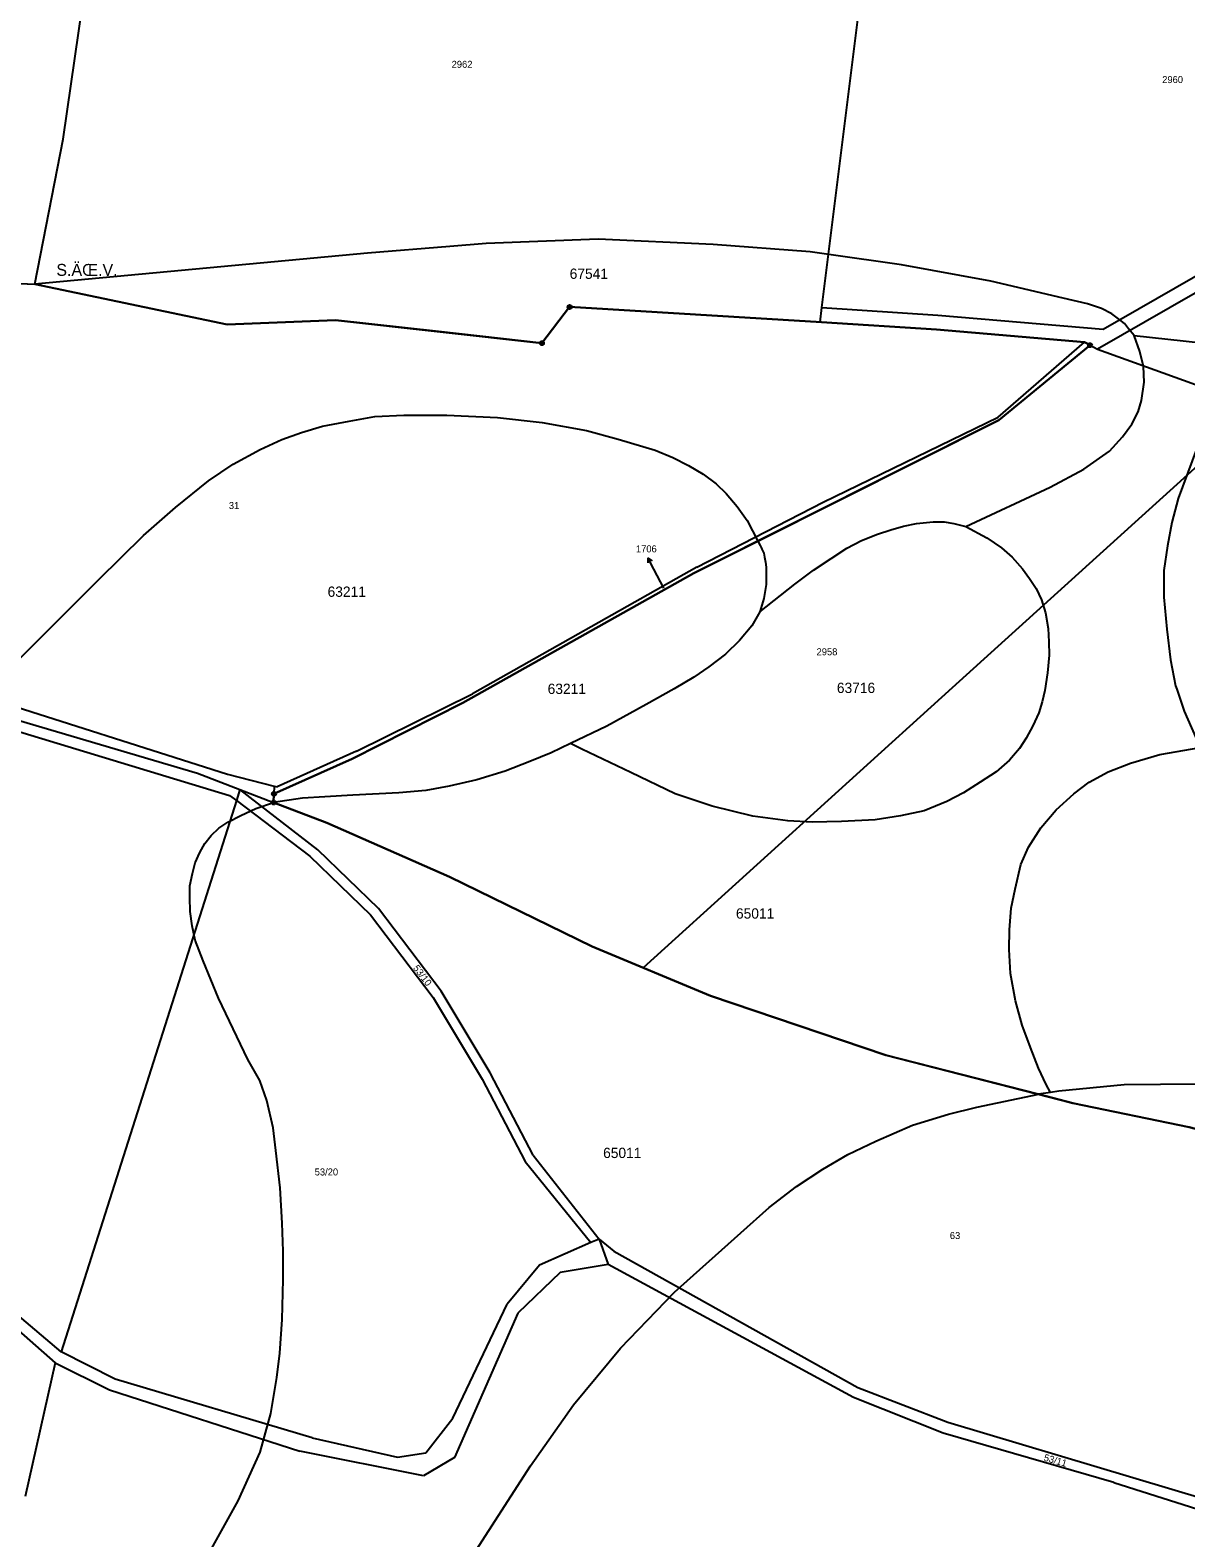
# Model space of a CAD drawing. Extents: x -546762 to -540209, y -1046851 to -1035694.
# Drawn here: x -544167.4 to -543886.8, y -1040941.9 to -1040575.9 of the extents above; entities that cross this region are included whole.
import ezdxf

# ---------------------------------------------------------------- set-up
doc = ezdxf.new("R2010")
doc.units = 0
for name, color, linetype in [('Vrstva 1', 7, 'Continuous'), ('Vrstva 13', 7, 'Continuous'), ('Vrstva 15', 7, 'Continuous'), ('Vrstva 16', 7, 'Continuous'), ('Vrstva 18', 7, 'Continuous'), ('Vrstva 24', 7, 'Continuous'), ('Vrstva 52', 7, 'Continuous'), ('Vrstva 53', 7, 'Continuous'), ('Vrstva 6', 7, 'Continuous')]:
    doc.layers.add(name, color=color, linetype=linetype)

msp = doc.modelspace()

# ---------------------------------------------------------------- linework, layer by layer
at = {"layer": 'Vrstva 1'}
for p, q in [((-543932.34, -1040669.86), (-543911.39, -1040651.66)), ((-544116.45, -1040760.23), (-544108.27, -1040763.37)), ((-544108.12, -1040759.38), (-544108.19, -1040761.26))]:
    msp.add_line(p, q, dxfattribs=at)
for points in [[(-543975.15, -1040643.22), (-543960.77, -1040527.96)], [(-543906.8, -1040648.49), (-543749.51, -1040558.14)], [(-543790.22, -1040585.7), (-543908.23, -1040653.37)], [(-543975.59, -1040646.75), (-543975.15, -1040643.22)], [(-543975.15, -1040643.22), (-543947.02, -1040645.05)], [(-543947.02, -1040645.05), (-543906.8, -1040648.49)], [(-543910.01, -1040652.36), (-543908.23, -1040653.37)], [(-543908.23, -1040653.37), (-543868.48, -1040667.62)], [(-543868.48, -1040667.62), (-543943.52, -1040735.55)], [(-543943.52, -1040735.55), (-544018.57, -1040803.47)], [(-544177.14, -1040885.51), (-544161.29, -1040899.35)], [(-544161.29, -1040899.35), (-544168.58, -1040931.83)]]:
    msp.add_lwpolyline(points, dxfattribs=at)
at = {"layer": 'Vrstva 13'}
msp.add_line((-544194.81, -1040636.28), (-544166.22, -1040637.59), dxfattribs=at)
for points in [[(-544159.37, -1040602.39), (-544152.78, -1040556.39)], [(-544166.22, -1040637.59), (-544159.37, -1040602.39)], [(-544166.22, -1040637.59), (-544119.59, -1040647.38)], [(-544166.22, -1040637.59), (-544119.59, -1040647.38)], [(-544036.41, -1040643.09), (-544043.13, -1040651.87)], [(-544036.41, -1040643.09), (-544043.13, -1040651.87)], [(-543975.59, -1040646.75), (-544036.41, -1040643.09)], [(-543975.59, -1040646.75), (-544036.41, -1040643.09)], [(-544119.59, -1040647.38), (-544093.27, -1040646.28)], [(-544119.59, -1040647.38), (-544093.27, -1040646.28)], [(-544043.13, -1040651.87), (-544093.27, -1040646.28)], [(-544043.13, -1040651.87), (-544093.27, -1040646.28)], [(-543975.26, -1040646.77), (-543975.59, -1040646.75)], [(-543975.26, -1040646.77), (-543975.59, -1040646.75)], [(-543975.26, -1040646.77), (-543947.29, -1040648.59)], [(-543975.26, -1040646.77), (-543947.29, -1040648.59)], [(-543947.29, -1040648.59), (-543911.39, -1040651.66)], [(-543947.29, -1040648.59), (-543911.39, -1040651.66)], [(-543910.01, -1040652.36), (-543932.13, -1040670.57)], [(-543910.01, -1040652.36), (-543932.13, -1040670.57)], [(-543910.01, -1040652.36), (-543911.39, -1040651.66)], [(-543910.01, -1040652.36), (-543911.39, -1040651.66)], [(-543932.13, -1040670.57), (-544006.25, -1040707.73)], [(-543932.13, -1040670.57), (-544006.25, -1040707.73)], [(-544006.25, -1040707.73), (-544062.36, -1040739.14)], [(-544006.25, -1040707.73), (-544062.36, -1040739.14)], [(-544062.36, -1040739.14), (-544089.23, -1040752.75)], [(-544062.36, -1040739.14), (-544089.23, -1040752.75)], [(-544108.19, -1040761.26), (-544089.23, -1040752.75)], [(-544108.19, -1040761.26), (-544089.23, -1040752.75)], [(-544108.27, -1040763.37), (-544108.19, -1040761.26)], [(-544108.27, -1040763.37), (-544108.19, -1040761.26)], [(-544095.39, -1040768.31), (-544108.27, -1040763.37)], [(-544095.39, -1040768.31), (-544108.27, -1040763.37)], [(-544095.39, -1040768.31), (-544065.53, -1040781.42)], [(-544095.39, -1040768.31), (-544065.53, -1040781.42)], [(-544065.53, -1040781.42), (-544030.94, -1040798.31)], [(-544065.53, -1040781.42), (-544030.94, -1040798.31)], [(-544018.57, -1040803.47), (-544030.94, -1040798.31)], [(-544018.57, -1040803.47), (-544030.94, -1040798.31)], [(-544002.2, -1040810.3), (-544018.57, -1040803.47)], [(-544002.2, -1040810.3), (-544018.57, -1040803.47)], [(-544002.2, -1040810.3), (-543959.63, -1040824.69)], [(-544002.2, -1040810.3), (-543959.63, -1040824.69)], [(-543959.63, -1040824.69), (-543914.18, -1040836.33)], [(-543959.63, -1040824.69), (-543914.18, -1040836.33)], [(-543914.18, -1040836.33), (-543885.98, -1040842.13)], [(-543914.18, -1040836.33), (-543885.98, -1040842.13)]]:
    msp.add_lwpolyline(points, dxfattribs=at)
at = {"layer": 'Vrstva 16'}
msp.add_line((-544015.93, -1040706.72), (-544017.29, -1040704.05), dxfattribs=at)
for points in [[(-544017.29, -1040705.17), (-544017.29, -1040704.05), (-544016.39, -1040704.71)], [(-544013.55, -1040711.37), (-544015.93, -1040706.72)]]:
    msp.add_lwpolyline(points, dxfattribs=at)
at = {"layer": 'Vrstva 24'}
for centre, radius in [((-544036.41, -1040643.09), 0.5), ((-544036.41, -1040643.09), 0.1), ((-544043.13, -1040651.87), 0.5), ((-544043.13, -1040651.87), 0.1), ((-543910.01, -1040652.36), 0.5), ((-543910.01, -1040652.36), 0.1), ((-544108.19, -1040761.26), 0.5), ((-544108.19, -1040761.26), 0.1), ((-544108.27, -1040763.37), 0.5), ((-544108.27, -1040763.37), 0.1)]:
    msp.add_circle(centre, radius, dxfattribs=at)
at = {"layer": 'Vrstva 52'}
for points in [[(-544166.22, -1040637.59), (-544159.37, -1040602.39), (-544152.78, -1040556.39), (-544148.25, -1040518.25), (-544148.05, -1040516.52), (-544147.1, -1040509.05), (-544119.61, -1040511.85), (-544114.36, -1040467.79), (-544109.21, -1040427.07), (-544107.28, -1040390.92), (-544084.37, -1040386.84), (-544033.06, -1040401.65), (-543986.48, -1040373.41), (-543990.67, -1040372.14), (-543961.4, -1040311.25), (-543946.79, -1040291.41)], [(-543910.66, -1040642.36), (-543916.57, -1040640.99), (-543934.09, -1040636.81), (-543955.78, -1040632.89), (-543973.45, -1040630.39), (-543978, -1040629.75), (-544001.53, -1040627.92), (-544029.5, -1040626.61), (-544056.68, -1040627.66), (-544065.45, -1040628.38), (-544085.44, -1040630.01), (-544166.22, -1040637.59)], [(-544297.7, -1040664.73), (-544298.67, -1040642.1), (-544267.15, -1040646.48), (-544246.26, -1040643.8), (-544216.62, -1040644.41), (-544194.81, -1040636.28), (-544166.22, -1040637.59)], [(-544166.22, -1040637.59), (-544119.59, -1040647.38), (-544093.27, -1040646.28), (-544043.13, -1040651.87), (-544036.41, -1040643.09), (-543975.26, -1040646.77), (-543947.29, -1040648.59), (-543911.39, -1040651.66), (-543910.01, -1040652.36), (-543932.13, -1040670.57), (-543990.72, -1040699.94)], [(-543990.71, -1040699.94), (-543932.13, -1040670.57), (-543910.01, -1040652.36), (-543911.39, -1040651.66), (-543947.29, -1040648.59), (-543975.26, -1040646.77), (-544036.41, -1040643.09), (-544043.13, -1040651.87), (-544068.2, -1040649.08), (-544093.27, -1040646.28), (-544119.59, -1040647.38), (-544166.22, -1040637.59)], [(-543899.3, -1040650.05), (-543900.69, -1040648.36), (-543901.69, -1040647.14), (-543903.46, -1040645.77), (-543904.77, -1040644.75), (-543907.24, -1040643.47), (-543910.66, -1040642.36)], [(-543940.17, -1040696.35), (-543919.71, -1040686.79), (-543911.49, -1040682.45), (-543905.28, -1040678.06), (-543902.12, -1040674.64), (-543899.9, -1040671.57), (-543898.36, -1040668.58), (-543897.51, -1040665.76), (-543896.91, -1040661.32), (-543897.08, -1040657.56), (-543897.94, -1040653.89), (-543899.3, -1040650.05)], [(-543899.3, -1040650.05), (-543874.8, -1040652.69)], [(-543874.8, -1040652.69), (-543882.91, -1040674.14), (-543888.66, -1040689.57), (-543890.15, -1040695.43), (-543891.2, -1040701.11), (-543892.09, -1040707.08), (-543892.09, -1040713.51), (-543891.35, -1040721.28), (-543890.45, -1040728.75), (-543889.26, -1040735.03), (-543888.98, -1040735.84), (-543887.17, -1040741.16), (-543883.28, -1040749.98)], [(-544176.07, -1040734.52), (-544150.81, -1040709.32), (-544139.86, -1040698.54), (-544132.11, -1040691.75), (-544124.12, -1040685.33), (-544118.06, -1040681.21), (-544111.52, -1040677.7), (-544106.32, -1040675.27), (-544101.47, -1040673.58), (-544096.39, -1040672), (-544089.97, -1040670.79), (-544083.67, -1040669.7), (-544076.65, -1040669.33), (-544066.23, -1040669.33), (-544053.88, -1040669.94), (-544043.1, -1040671.15), (-544032.32, -1040673.09), (-544024.57, -1040675.15), (-544015.61, -1040677.82), (-544011.3, -1040679.63), (-544007.49, -1040681.57), (-544003.96, -1040683.65), (-544000.85, -1040686), (-543998.36, -1040688.36), (-543995.73, -1040691.54), (-543993.31, -1040694.94), (-543990.72, -1040699.94)], [(-543990.18, -1040717.05), (-543981.69, -1040710.41), (-543977.16, -1040706.99), (-543972.91, -1040704.11), (-543969.06, -1040701.63), (-543965.5, -1040699.77), (-543961.65, -1040698.21), (-543958.38, -1040697.18), (-543955.36, -1040696.31), (-543952.19, -1040695.67), (-543948.14, -1040695.28), (-543945.41, -1040695.28), (-543943.06, -1040695.62), (-543940.17, -1040696.35)], [(-543940.17, -1040696.35), (-543935.12, -1040699.16), (-543931.54, -1040701.55), (-543928.95, -1040703.79), (-543926.41, -1040706.62), (-543924.71, -1040708.96), (-543923.1, -1040711.4), (-543921.78, -1040714.14), (-543920.81, -1040717.36), (-543920.23, -1040721.14), (-543919.99, -1040724.36), (-543919.94, -1040727.63), (-543920.33, -1040731.88), (-543921.01, -1040736.17), (-543921.61, -1040738.91), (-543922.44, -1040741.64), (-543923.95, -1040744.77), (-543925.51, -1040747.74), (-543927.17, -1040750.28), (-543929.56, -1040753.11), (-543932.83, -1040755.89), (-543936.68, -1040758.43), (-543940.73, -1040761.06), (-543944.78, -1040763.11), (-543950.3, -1040765.4), (-543956.02, -1040766.6), (-543962.17, -1040767.54), (-543970.36, -1040767.96)], [(-543990.72, -1040699.94), (-544006.25, -1040707.73), (-544062.36, -1040739.14), (-544089.23, -1040752.75), (-544108.19, -1040761.26), (-544108.27, -1040763.37)], [(-544108.27, -1040763.37), (-544108.19, -1040761.26), (-544089.23, -1040752.75), (-544062.36, -1040739.14), (-544006.25, -1040707.73), (-543990.71, -1040699.94)], [(-543990.71, -1040699.94), (-543990.13, -1040700.99), (-543989.82, -1040701.67), (-543989.71, -1040701.91), (-543989.26, -1040702.89), (-543989.04, -1040703.86), (-543988.82, -1040705.03), (-543988.68, -1040706.26), (-543988.65, -1040708), (-543988.65, -1040710.47), (-543989.24, -1040713.89), (-543990.18, -1040717.05)], [(-543990.18, -1040717.05), (-543992.15, -1040720.47), (-543995.13, -1040724.05), (-543998.55, -1040727.38), (-544002.56, -1040730.46), (-544006.27, -1040732.95), (-544010.97, -1040735.77), (-544017.8, -1040739.61), (-544027.36, -1040744.82), (-544036.21, -1040749.01)], [(-544036.21, -1040749.01), (-544040.9, -1040751.32), (-544046.02, -1040753.45), (-544052.08, -1040755.76), (-544058.91, -1040757.89), (-544065.65, -1040759.43), (-544071.29, -1040760.45), (-544077.86, -1040761.05), (-544089.04, -1040761.56), (-544095.87, -1040761.99), (-544101.25, -1040762.33)], [(-543970.36, -1040767.96), (-543977.53, -1040768.13), (-543983.42, -1040767.79), (-543991.87, -1040766.68), (-544001.77, -1040764.29), (-544010.73, -1040761.3), (-544021.57, -1040756.09), (-544033.44, -1040750.46), (-544036.21, -1040749.01)], [(-543918.25, -1040765.13), (-543913.99, -1040761.29), (-543910.23, -1040758.47), (-543905.62, -1040755.91), (-543900.16, -1040753.86), (-543893.08, -1040751.72), (-543883.28, -1040749.98)], [(-544101.25, -1040762.33), (-544108.27, -1040763.37)], [(-544138.26, -1040971.27), (-544116.85, -1040932.89), (-544111.56, -1040921.02), (-544108.95, -1040911.66), (-544107.5, -1040902.93), (-544106.77, -1040896.99), (-544106.17, -1040888.88), (-544105.92, -1040879.18), (-544105.92, -1040872.27), (-544106.17, -1040865.49), (-544106.65, -1040856.89), (-544107.74, -1040847.8), (-544108.35, -1040842.35), (-544109.92, -1040835.68), (-544111.62, -1040830.83), (-544114.52, -1040825.72), (-544121.65, -1040810.83), (-544125.38, -1040801.76), (-544127.32, -1040796.78), (-544128.08, -1040793.31), (-544128.5, -1040789.85), (-544128.64, -1040786.39), (-544128.64, -1040783.62), (-544128.01, -1040780.57), (-544127.32, -1040778.01), (-544126.21, -1040775.52), (-544124.97, -1040773.3), (-544123.45, -1040771.36), (-544121.58, -1040769.63), (-544119.42, -1040768.11), (-544116.27, -1040766.53), (-544112.63, -1040764.84), (-544108.27, -1040763.37)], [(-544108.27, -1040763.37), (-544095.39, -1040768.31)], [(-543922.54, -1040834.19), (-543959.63, -1040824.69), (-544002.2, -1040810.3), (-544030.94, -1040798.31), (-544065.53, -1040781.42), (-544095.39, -1040768.31), (-544108.27, -1040763.37)], [(-543919.6, -1040833.75), (-543920.66, -1040831.83), (-543922.5, -1040827.86), (-543924.46, -1040822.82), (-543926.51, -1040817.44), (-543928.13, -1040811.47), (-543929.33, -1040804.89), (-543929.67, -1040799.08), (-543929.61, -1040794.25), (-543929.18, -1040789.04), (-543928.24, -1040784.43), (-543926.79, -1040778.45), (-543925, -1040774.18), (-543922.01, -1040769.49), (-543918.25, -1040765.13)], [(-544095.39, -1040768.31), (-544065.53, -1040781.42), (-544030.94, -1040798.31), (-544002.2, -1040810.3), (-543959.63, -1040824.69), (-543922.49, -1040834.2)], [(-543922.49, -1040834.2), (-543914.18, -1040836.33), (-543885.98, -1040842.13), (-543861.85, -1040848.48), (-543825.12, -1040858.15), (-543769.53, -1040871.92), (-543756.76, -1040874.7), (-543744.71, -1040877.32), (-543722.63, -1040842.84), (-543714.73, -1040829.47), (-543702.42, -1040808.65)], [(-543772.11, -1040865.35), (-543775.52, -1040863.27), (-543787.17, -1040856.55), (-543801.07, -1040849.67), (-543814.36, -1040843.55), (-543825.41, -1040839.66), (-543841.84, -1040835.92), (-543854.09, -1040833.68), (-543858.8, -1040833.16), (-543868.88, -1040832.04), (-543884.11, -1040831.74), (-543901.74, -1040831.89), (-543917.64, -1040833.46), (-543919.6, -1040833.75)], [(-544060.71, -1040947.31), (-544045.88, -1040924.4), (-544035.49, -1040909.56), (-544024.05, -1040895.78), (-544010.91, -1040882.21), (-543994.8, -1040867.79), (-543987.98, -1040861.66), (-543981.32, -1040856.57), (-543974.9, -1040852.33), (-543968.85, -1040848.82), (-543962.06, -1040845.55), (-543953.1, -1040841.67), (-543944.38, -1040839), (-543937.48, -1040837.31), (-543922.49, -1040834.2)], [(-543919.6, -1040833.75), (-543922.54, -1040834.19)], [(-543756.76, -1040874.7), (-543769.53, -1040871.92), (-543825.12, -1040858.15), (-543859.1, -1040849.21), (-543861.85, -1040848.48), (-543885.98, -1040842.13), (-543914.18, -1040836.33), (-543922.54, -1040834.19)]]:
    msp.add_lwpolyline(points, dxfattribs=at)
at = {"layer": 'Vrstva 6'}
for points in [[(-543974.83, -1040690.48), (-543932.34, -1040669.86)], [(-544005.53, -1040706.26), (-543974.83, -1040690.48)], [(-544005.53, -1040706.26), (-544059.96, -1040737)], [(-544181.1, -1040740.22), (-544126.75, -1040756.28)], [(-544179.99, -1040737.25), (-544119.51, -1040756.46)], [(-544088.15, -1040750.94), (-544059.96, -1040737)], [(-544184.63, -1040741.8), (-544118.95, -1040761.66)], [(-544088.15, -1040750.94), (-544107.4, -1040759.56)], [(-544126.75, -1040756.28), (-544116.45, -1040760.23)], [(-544119.51, -1040756.46), (-544108.12, -1040759.38)], [(-544118.95, -1040761.66), (-544117.3, -1040762.91)], [(-544116.45, -1040760.23), (-544117.3, -1040762.91)], [(-544097.51, -1040774.82), (-544116.45, -1040760.23)], [(-544108.12, -1040759.38), (-544107.4, -1040759.56)], [(-544117.3, -1040762.91), (-544159.89, -1040896.7)], [(-544117.3, -1040762.91), (-544099.47, -1040776.36)], [(-544099.47, -1040776.36), (-544084.74, -1040790.61)], [(-544082.77, -1040789.07), (-544097.51, -1040774.82)], [(-544084.74, -1040790.61), (-544069.54, -1040810.72)], [(-544067.58, -1040809.17), (-544082.77, -1040789.07)], [(-544055.69, -1040829.02), (-544067.58, -1040809.17)], [(-544069.54, -1040810.72), (-544057.66, -1040830.56)], [(-544057.66, -1040830.56), (-544047.18, -1040850.49)], [(-544045.21, -1040848.95), (-544055.69, -1040829.02)], [(-544045.21, -1040848.95), (-544029.25, -1040869.32)], [(-544047.18, -1040850.49), (-544031.22, -1040870.19)], [(-544031.22, -1040870.19), (-544043.7, -1040875.69)], [(-544029.25, -1040869.32), (-544031.22, -1040870.19)], [(-544029.25, -1040869.32), (-544025.67, -1040872.29)], [(-544029.25, -1040869.32), (-544027.05, -1040875.5)], [(-544025.67, -1040872.29), (-543966.41, -1040905.34)], [(-544043.7, -1040875.69), (-544051.57, -1040885.14)], [(-544027.05, -1040875.5), (-544038.71, -1040877.43)], [(-543967.48, -1040907.82), (-544027.05, -1040875.5)], [(-544038.71, -1040877.43), (-544049.01, -1040887.29)], [(-544159.89, -1040896.7), (-544175.93, -1040883.2)], [(-544064.79, -1040912.79), (-544051.57, -1040885.14)], [(-544049.01, -1040887.29), (-544064.37, -1040922.31)], [(-544146.73, -1040903.3), (-544159.89, -1040896.7)], [(-544161.29, -1040899.35), (-544148.13, -1040905.96)], [(-544098.91, -1040917.61), (-544146.73, -1040903.3)], [(-544148.13, -1040905.96), (-544101.93, -1040920.81)], [(-543945.65, -1040916.41), (-543967.48, -1040907.82)], [(-543966.41, -1040905.34), (-543944.52, -1040913.8)], [(-544071.31, -1040921.21), (-544064.79, -1040912.79)], [(-543944.52, -1040913.8), (-543854.68, -1040940.67)], [(-544098.91, -1040917.61), (-544078.18, -1040922.27)], [(-543904.23, -1040928.44), (-543945.65, -1040916.41)], [(-544071.84, -1040926.76), (-544101.93, -1040920.81)], [(-544078.18, -1040922.27), (-544071.31, -1040921.21)], [(-544064.37, -1040922.31), (-544071.84, -1040926.76)], [(-543904.23, -1040928.44), (-543855.24, -1040943.92)]]:
    msp.add_lwpolyline(points, dxfattribs=at)

# ---------------------------------------------------------------- texts
at = {"layer": 'Vrstva 15'}
msp.add_text('S.ÄŒ.V.', height=2.9, dxfattribs=at).set_placement((-544161.03, -1040635.54))
at = {"layer": 'Vrstva 16'}
msp.add_text('1706', height=1.7, dxfattribs=at).set_placement((-544020.3, -1040702.66))
at = {"layer": 'Vrstva 18'}
for s, height, p in [('2962', 1.7, (-544065.05, -1040585.05)), ('2960', 1.7, (-543892.5, -1040588.75)), ('31', 1.7, (-544119.14, -1040692.13)), ('1706', 0.1, (-544013.68, -1040711.37)), ('2958', 1.7, (-543976.43, -1040727.63)), ('53/20', 1.7, (-544098.3, -1040853.89)), ('63', 1.7, (-543944.07, -1040869.33))]:
    msp.add_text(s, height=height, dxfattribs=at).set_placement(p)
for s, rotation, p in [('53/10', 307.2011, (-544074.53, -1040803.59)), ('53/11', 344.1304, (-543921.39, -1040923.09))]:
    msp.add_text(s, height=1.7, rotation=rotation, dxfattribs=at).set_placement(p)
at = {"layer": 'Vrstva 53'}
for s, p in [('67541', (-544036.38, -1040636.27)), ('63211', (-544095.17, -1040713.45)), ('63211', (-544041.73, -1040737.02)), ('63716', (-543971.5, -1040736.79)), ('65011', (-543996, -1040791.55)), ('65011', (-544028.26, -1040849.66))]:
    msp.add_text(s, height=2.5, dxfattribs=at).set_placement(p)

doc.saveas('drawing.dxf')
